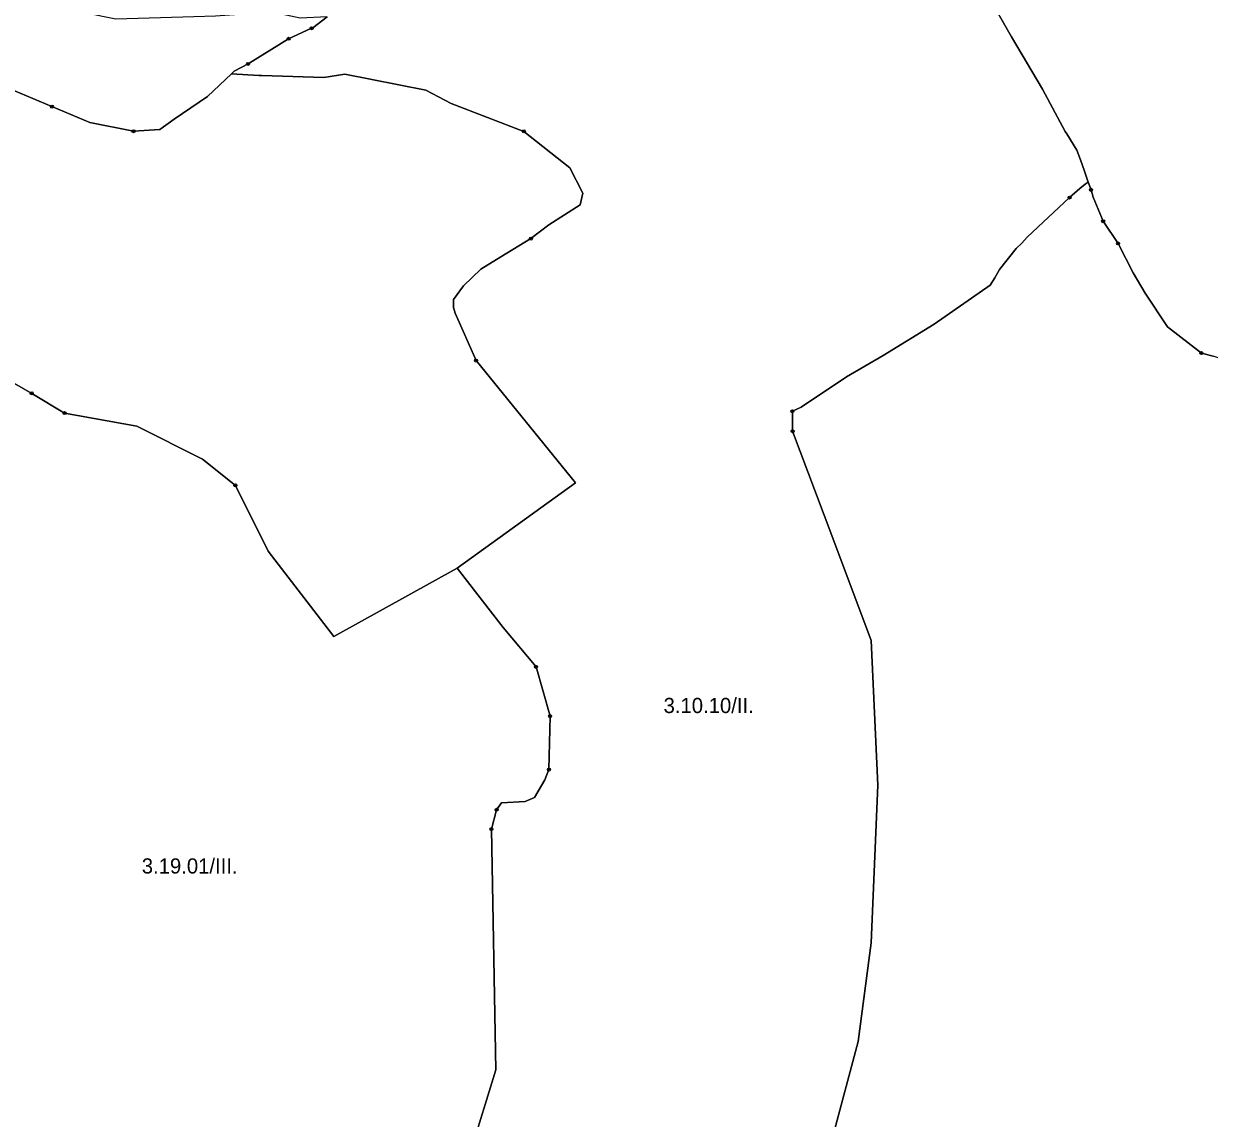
# Model space of a CAD drawing. Extents: x -650455 to -642254, y -1075222 to -1066610.
# Drawn here: x -646705 to -645923, y -1071216 to -1070494 of the extents above; entities that cross this region are included whole.
import ezdxf
from ezdxf.enums import TextEntityAlignment as Align

# ---------------------------------------------------------------- set-up
doc = ezdxf.new("R2010")
doc.units = 0
doc.header["$LTSCALE"] = 4
doc.header["$PDMODE"] = 32
doc.header["$PDSIZE"] = 2
for name, color, linetype, lineweight in [('1', 7, 'Continuous', 25), ('11', 7, 'Continuous', 13), ('12', 7, 'Continuous', 13), ('13', 7, 'Continuous', 13), ('14', 7, 'Continuous', 13)]:
    doc.layers.add(name, color=color, linetype=linetype, lineweight=lineweight)
doc.layers.add('2', color=7, linetype='Continuous')

msp = doc.modelspace()

# ---------------------------------------------------------------- linework, layer by layer
at = {"layer": '1'}
for points in [[(-646071.795, -1070469.988), (-646053.095, -1070503.139), (-646032.694, -1070537.65), (-646017.857, -1070565.514), (-646016.721, -1070567.029), (-646009.999, -1070577.784), (-646007.731, -1070584.143), (-646005.067, -1070591.608), (-646002.692, -1070598.86)], [(-645920.242, -1070713.679), (-645927.962, -1070711.588), (-645950.317, -1070694.38), (-645965.032, -1070672.106), (-645972.912, -1070658.757), (-645982.884, -1070639.297), (-645992.731, -1070624.604), (-645999.333, -1070608.761), (-646000.735, -1070603.916), (-646002.692, -1070598.86), (-646005.067, -1070591.608), (-646007.731, -1070584.143), (-646009.999, -1070577.784), (-646016.721, -1070567.029), (-646017.857, -1070565.514), (-646032.694, -1070537.65), (-646053.095, -1070503.139), (-646071.795, -1070469.988)], [(-646504.412, -1070489.744), (-646513.93, -1070496.996), (-646514.69, -1070497.343), (-646529.926, -1070504.299), (-646556.587, -1070520.875), (-646565.86, -1070525.744), (-646567.608, -1070527.409), (-646583.248, -1070542.32), (-646605.272, -1070557.273), (-646614.777, -1070564.228), (-646632.165, -1070565.271), (-646660.912, -1070559.591), (-646685.95, -1070549.043), (-646710.988, -1070538.494)], [(-646549.577, -1070528.482), (-646567.608, -1070527.409), (-646565.86, -1070525.744), (-646556.587, -1070520.875), (-646529.926, -1070504.299), (-646514.69, -1070497.343), (-646513.93, -1070496.996), (-646504.412, -1070489.744)], [(-646567.608, -1070527.409), (-646549.577, -1070528.482), (-646547.526, -1070528.604), (-646506.551, -1070529.81), (-646492.812, -1070527.641), (-646439.304, -1070538.246), (-646422.673, -1070546.923), (-646374.709, -1070565.361), (-646344.339, -1070589.464), (-646335.903, -1070606.095), (-646337.59, -1070613.808), (-646358.319, -1070626.944), (-646370.129, -1070636.103), (-646389.894, -1070648.154), (-646403.15, -1070656.349), (-646414.478, -1070667.195), (-646421.227, -1070676.355), (-646421.227, -1070681.416), (-646420.044, -1070685.202), (-646406.218, -1070716.568), (-646340.708, -1070797.189), (-646418.709, -1070853.523), (-646499.959, -1070898.482), (-646543.293, -1070842.148), (-646564.96, -1070798.814), (-646586.627, -1070781.481), (-646629.961, -1070759.814), (-646677.628, -1070751.147), (-646699.295, -1070738.147), (-646729.628, -1070720.814)], [(-646660.912, -1070559.591), (-646632.165, -1070565.271), (-646614.777, -1070564.228), (-646605.272, -1070557.273), (-646583.248, -1070542.32), (-646567.608, -1070527.409)], [(-646410.042, -1071239.194), (-646393.156, -1071184.317), (-646396.096, -1071025.528), (-646392.694, -1071012.768), (-646389.49, -1071008.069), (-646373.899, -1071007.215), (-646367.706, -1071004.652), (-646360.872, -1070992.906), (-646358.26, -1070986.275), (-646357.431, -1070950.993), (-646366.708, -1070918.524), (-646388.375, -1070892.524), (-646418.709, -1070853.523), (-646340.708, -1070797.189), (-646406.218, -1070716.568), (-646420.044, -1070685.202), (-646421.227, -1070681.416), (-646421.227, -1070676.355), (-646414.478, -1070667.195), (-646403.15, -1070656.349), (-646389.894, -1070648.154), (-646370.129, -1070636.103), (-646358.319, -1070626.944), (-646337.59, -1070613.808), (-646335.903, -1070606.095), (-646344.339, -1070589.464), (-646374.709, -1070565.361), (-646422.673, -1070546.923), (-646439.304, -1070538.246), (-646492.812, -1070527.641), (-646506.551, -1070529.81), (-646547.526, -1070528.604), (-646549.577, -1070528.482)], [(-646710.988, -1070538.494), (-646685.95, -1070549.043), (-646660.912, -1070559.591)], [(-646171.706, -1071230.527), (-646154.372, -1071165.527), (-646145.706, -1071100.526), (-646141.372, -1070996.525), (-646145.706, -1070901.191), (-646171.706, -1070831.857), (-646197.487, -1070763.107), (-646197.659, -1070749.898), (-646191.877, -1070747.27), (-646161.913, -1070727.294), (-646137.732, -1070713.101), (-646104.089, -1070692.599), (-646067.291, -1070666.841), (-646064.224, -1070661.984), (-646061.077, -1070656.455), (-646050.02, -1070642.533), (-646046.389, -1070639.184), (-646042.918, -1070635.189), (-646014.913, -1070609.041), (-646008.134, -1070603.149), (-646004.664, -1070600.284), (-646002.692, -1070598.86), (-646000.735, -1070603.916), (-645999.333, -1070608.761), (-645992.731, -1070624.604), (-645982.884, -1070639.297), (-645972.912, -1070658.757), (-645965.032, -1070672.106), (-645950.317, -1070694.38), (-645927.962, -1070711.588), (-645920.242, -1070713.679)], [(-646002.692, -1070598.86), (-646004.664, -1070600.284), (-646008.134, -1070603.149), (-646014.913, -1070609.041), (-646042.918, -1070635.189), (-646046.389, -1070639.184), (-646050.02, -1070642.533), (-646061.077, -1070656.455), (-646064.224, -1070661.984), (-646067.291, -1070666.841), (-646104.089, -1070692.599), (-646137.732, -1070713.101), (-646161.913, -1070727.294), (-646191.877, -1070747.27), (-646197.659, -1070749.898), (-646197.487, -1070763.107), (-646171.706, -1070831.857), (-646145.706, -1070901.191), (-646141.372, -1070996.525), (-646145.706, -1071100.526), (-646154.372, -1071165.527), (-646171.706, -1071230.527)], [(-646729.628, -1070720.814), (-646699.295, -1070738.147), (-646677.628, -1070751.147), (-646629.961, -1070759.814), (-646586.627, -1070781.481), (-646564.96, -1070798.814), (-646543.293, -1070842.148), (-646499.959, -1070898.482), (-646418.709, -1070853.523)], [(-646418.709, -1070853.523), (-646388.375, -1070892.524), (-646366.708, -1070918.524), (-646357.431, -1070950.993), (-646358.26, -1070986.275), (-646360.872, -1070992.906), (-646367.706, -1071004.652), (-646373.899, -1071007.215), (-646389.49, -1071008.069), (-646392.694, -1071012.768), (-646396.096, -1071025.528), (-646393.156, -1071184.317), (-646410.042, -1071239.194)]]:
    msp.add_lwpolyline(points, dxfattribs=at)
at = {"layer": '11'}
msp.add_line((-645982.884, -1070639.297), (-645992.731, -1070624.604), dxfattribs=at)
for points in [[(-645992.731, -1070624.604), (-645999.333, -1070608.761), (-646000.735, -1070603.916), (-646002.692, -1070598.86), (-646004.664, -1070600.284), (-646008.134, -1070603.149), (-646014.913, -1070609.041), (-646042.918, -1070635.189), (-646046.389, -1070639.184), (-646050.02, -1070642.533), (-646061.077, -1070656.455), (-646064.224, -1070661.984), (-646067.291, -1070666.841), (-646104.089, -1070692.599), (-646137.732, -1070713.101), (-646161.913, -1070727.294), (-646191.877, -1070747.27), (-646197.659, -1070749.898), (-646197.487, -1070763.107)], [(-645927.962, -1070711.588), (-645950.317, -1070694.38), (-645965.032, -1070672.106), (-645972.912, -1070658.757), (-645982.884, -1070639.297)], [(-645880.438, -1070727.108), (-645920.242, -1070713.679), (-645927.962, -1070711.588)], [(-646197.487, -1070763.107), (-646171.706, -1070831.857), (-646145.706, -1070901.191), (-646141.372, -1070996.525), (-646145.706, -1071100.526), (-646154.372, -1071165.527), (-646171.706, -1071230.527), (-646197.706, -1071286.861)]]:
    msp.add_lwpolyline(points, dxfattribs=at)
for p in [(-645992.731, -1070624.604), (-645982.884, -1070639.297), (-645927.962, -1070711.588), (-646197.487, -1070763.107)]:
    msp.add_point(p, dxfattribs=at)
at = {"layer": '12'}
for p, q in [((-646366.708, -1070918.524), (-646357.431, -1070950.993)), ((-646357.431, -1070950.993), (-646358.26, -1070986.275))]:
    msp.add_line(p, q, dxfattribs=at)
for points in [[(-646083.647, -1070291.36), (-646105.207, -1070307.24), (-646126.536, -1070324.744), (-646135.809, -1070325.671), (-646149.487, -1070331.235), (-646157.707, -1070337.514), (-646137.077, -1070343.504), (-646120.077, -1070366.964), (-646108.856, -1070380.565), (-646102.056, -1070390.425), (-646091.516, -1070416.436), (-646087.776, -1070430.716), (-646071.795, -1070469.988), (-646053.095, -1070503.139), (-646032.694, -1070537.65), (-646017.857, -1070565.514), (-646016.721, -1070567.029), (-646009.999, -1070577.784), (-646007.731, -1070584.143), (-646005.067, -1070591.608), (-646002.692, -1070598.86), (-646000.735, -1070603.916)], [(-646014.913, -1070609.041), (-646008.134, -1070603.149), (-646004.664, -1070600.284), (-646002.692, -1070598.86), (-646005.067, -1070591.608), (-646007.731, -1070584.143), (-646009.999, -1070577.784), (-646016.721, -1070567.029), (-646017.857, -1070565.514), (-646032.694, -1070537.65), (-646053.095, -1070503.139), (-646071.795, -1070469.988), (-646087.776, -1070430.716), (-646091.516, -1070416.436), (-646102.056, -1070390.425), (-646108.856, -1070380.565), (-646120.077, -1070366.964)], [(-646504.412, -1070489.744), (-646513.93, -1070496.996), (-646514.69, -1070497.343), (-646529.926, -1070504.299)], [(-646529.926, -1070504.299), (-646556.587, -1070520.875), (-646565.86, -1070525.744), (-646567.608, -1070527.409), (-646549.577, -1070528.482), (-646547.526, -1070528.604), (-646506.551, -1070529.81), (-646492.812, -1070527.641), (-646439.304, -1070538.246), (-646422.673, -1070546.923), (-646374.709, -1070565.361)], [(-646374.709, -1070565.361), (-646344.339, -1070589.464), (-646335.903, -1070606.095), (-646337.59, -1070613.808), (-646358.319, -1070626.944), (-646370.129, -1070636.103), (-646389.894, -1070648.154), (-646403.15, -1070656.349), (-646414.478, -1070667.195), (-646421.227, -1070676.355), (-646421.227, -1070681.416), (-646420.044, -1070685.202), (-646406.218, -1070716.568), (-646340.708, -1070797.189), (-646418.709, -1070853.523), (-646388.375, -1070892.524), (-646366.708, -1070918.524)], [(-646000.735, -1070603.916), (-645999.333, -1070608.761), (-645992.731, -1070624.604), (-645982.884, -1070639.297)], [(-646197.659, -1070749.898), (-646191.877, -1070747.27), (-646161.913, -1070727.294), (-646137.732, -1070713.101), (-646104.089, -1070692.599), (-646067.291, -1070666.841), (-646064.224, -1070661.984), (-646061.077, -1070656.455), (-646050.02, -1070642.533), (-646046.389, -1070639.184), (-646042.918, -1070635.189), (-646014.913, -1070609.041)], [(-645982.884, -1070639.297), (-645972.912, -1070658.757), (-645965.032, -1070672.106), (-645950.317, -1070694.38), (-645927.962, -1070711.588), (-645920.242, -1070713.679)], [(-646171.706, -1071230.527), (-646154.372, -1071165.527), (-646145.706, -1071100.526), (-646141.372, -1070996.525), (-646145.706, -1070901.191), (-646171.706, -1070831.857), (-646197.487, -1070763.107), (-646197.659, -1070749.898)], [(-646358.26, -1070986.275), (-646360.872, -1070992.906), (-646367.706, -1071004.652), (-646373.899, -1071007.215), (-646389.49, -1071008.069), (-646392.694, -1071012.768), (-646396.096, -1071025.528)], [(-646396.096, -1071025.528), (-646393.156, -1071184.317), (-646410.042, -1071239.194)]]:
    msp.add_lwpolyline(points, dxfattribs=at)
for p in [(-646529.926, -1070504.299), (-646374.709, -1070565.361), (-646014.913, -1070609.041), (-646000.735, -1070603.916), (-645982.884, -1070639.297), (-646197.659, -1070749.898), (-646366.708, -1070918.524), (-646357.431, -1070950.993), (-646358.26, -1070986.275), (-646396.096, -1071025.528)]:
    msp.add_point(p, dxfattribs=at)
at = {"layer": '13'}
for points in [[(-646632.165, -1070565.271), (-646660.912, -1070559.591), (-646685.95, -1070549.043), (-646710.988, -1070538.494), (-646736.258, -1070527.946), (-646762.919, -1070520.643)], [(-646370.129, -1070636.103), (-646358.319, -1070626.944), (-646337.59, -1070613.808), (-646335.903, -1070606.095), (-646344.339, -1070589.464), (-646374.709, -1070565.361), (-646422.673, -1070546.923), (-646439.304, -1070538.246), (-646492.812, -1070527.641), (-646506.551, -1070529.81), (-646547.526, -1070528.604), (-646549.577, -1070528.482), (-646567.608, -1070527.409), (-646583.248, -1070542.32), (-646605.272, -1070557.273), (-646614.777, -1070564.228), (-646632.165, -1070565.271)], [(-646406.218, -1070716.568), (-646420.044, -1070685.202), (-646421.227, -1070681.416), (-646421.227, -1070676.355), (-646414.478, -1070667.195), (-646403.15, -1070656.349), (-646389.894, -1070648.154), (-646370.129, -1070636.103)], [(-646699.295, -1070738.147), (-646677.628, -1070751.147), (-646629.961, -1070759.814), (-646586.627, -1070781.481), (-646564.96, -1070798.814), (-646543.293, -1070842.148), (-646499.959, -1070898.482), (-646418.709, -1070853.523), (-646340.708, -1070797.189), (-646406.218, -1070716.568)], [(-646677.628, -1070751.147), (-646699.295, -1070738.147), (-646729.628, -1070720.814), (-646751.296, -1070768.481), (-646768.629, -1070811.815), (-646799.029, -1070883.683), (-646815.187, -1070905.227), (-646831.346, -1070932.158), (-646869.049, -1070964.475), (-646804.415, -1071034.495), (-646782.712, -1071061.526), (-646782.712, -1071100.526), (-646769.712, -1071135.193), (-646743.712, -1071187.194), (-646708.811, -1071237.149)], [(-646751.296, -1070768.481), (-646729.628, -1070720.814), (-646699.295, -1070738.147)], [(-646564.96, -1070798.814), (-646586.627, -1070781.481), (-646629.961, -1070759.814), (-646677.628, -1070751.147)], [(-646366.708, -1070918.524), (-646388.375, -1070892.524), (-646418.709, -1070853.523), (-646499.959, -1070898.482), (-646543.293, -1070842.148), (-646564.96, -1070798.814)], [(-646392.694, -1071012.768), (-646389.49, -1071008.069), (-646373.899, -1071007.215), (-646367.706, -1071004.652), (-646360.872, -1070992.906), (-646358.26, -1070986.275), (-646357.431, -1070950.993), (-646366.708, -1070918.524)], [(-646410.042, -1071239.194), (-646393.156, -1071184.317), (-646396.096, -1071025.528), (-646392.694, -1071012.768)]]:
    msp.add_lwpolyline(points, dxfattribs=at)
for p in [(-646632.165, -1070565.271), (-646370.129, -1070636.103), (-646406.218, -1070716.568), (-646699.295, -1070738.147), (-646677.628, -1070751.147), (-646564.96, -1070798.814), (-646366.708, -1070918.524), (-646392.694, -1071012.768)]:
    msp.add_point(p, dxfattribs=at)
at = {"layer": '14'}
for points in [[(-646514.69, -1070497.343), (-646513.93, -1070496.996), (-646504.412, -1070489.744), (-646522.293, -1070490.738), (-646540.7, -1070486.685), (-646578.106, -1070489.302), (-646592.291, -1070489.809), (-646643.714, -1070491.413), (-646664.401, -1070487.107), (-646680.613, -1070473.935), (-646689.056, -1070460.931), (-646689.394, -1070455.19), (-646688.291, -1070450.623), (-646683.243, -1070441.891), (-646682.529, -1070440.373), (-646690.65, -1070432.527), (-646698.336, -1070425.54), (-646716.085, -1070418.622), (-646733.694, -1070416.456), (-646751.583, -1070414.289), (-646769.192, -1070417.294)], [(-646556.587, -1070520.875), (-646529.926, -1070504.299), (-646514.69, -1070497.343)], [(-646762.919, -1070520.643), (-646736.258, -1070527.946), (-646710.988, -1070538.494), (-646685.95, -1070549.043)], [(-646685.95, -1070549.043), (-646660.912, -1070559.591), (-646632.165, -1070565.271), (-646614.777, -1070564.228), (-646605.272, -1070557.273), (-646583.248, -1070542.32), (-646567.608, -1070527.409), (-646565.86, -1070525.744), (-646556.587, -1070520.875)]]:
    msp.add_lwpolyline(points, dxfattribs=at)
for p in [(-646514.69, -1070497.343), (-646556.587, -1070520.875), (-646685.95, -1070549.043)]:
    msp.add_point(p, dxfattribs=at)

# ---------------------------------------------------------------- texts
at = {"layer": '2'}
for s, p in [('3.10.10/II.', (-646252.865, -1070948.965)), ('3.19.01/III.', (-646595.105, -1071054.789))]:
    msp.add_text(s, height=10, dxfattribs=at).set_placement(p, align=Align.CENTER)

doc.saveas('drawing.dxf')
